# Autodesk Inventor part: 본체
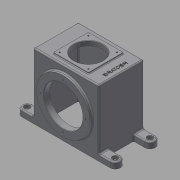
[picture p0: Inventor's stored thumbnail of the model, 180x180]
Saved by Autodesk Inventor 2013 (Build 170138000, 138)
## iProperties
Created: 2016-11
Part Number: 본체
Material: 일반
Document SubType Name: Modeling
Designer: mduedu
Density: 1 g/cm^3
Author: mduedu
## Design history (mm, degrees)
sketch "스케치1"
  geometry: L1 (-80, 0)-(80, 0); L2 (80, 0)-(80, 160); L3 (80, 160)-(-80, 160); L4 (-80, 160)-(-80, 0); 2 further points
  constraints: 8 end point, 2 parallel, 1 coincident, 1 horizontal, 1 midpoint, 1 perpendicular
  dimensions: "d0" = 160 distance of L2.end L3.end; "d2" = 160 distance of L1.end L2.end
extrude "돌출1" new body sketch "스케치1" stored distance "d3" = 110; taper "d4" = 0 deg
sketch "스케치2"
  geometry: L1 (-80, -55)-(-80, 55) reference; L2 (-80, -55)-(-120, -55); L3 (-120, -55)-(-120, 55); L4 (-120, 55)-(-80, 55); L5 (-80, 55)-(-80, -55); 1 further point
  constraints: 8 end point, 2 parallel, 1 horizontal, 1 perpendicular
  dimensions: "d5" = 40 distance of L1.end L3.end
extrude "돌출2" join sketch "스케치2" distance "d6" = 15; taper "d7" = 0 deg
sketch "스케치3"
  geometry: L1 (80, 55)-(80, -55) reference; L2 (120, -55)-(120, 55) reference; L3 (80, 30)-(120, 30); L4 (120, 30)-(120, -30); L5 (120, -30)-(80, -30); L6 (80, -30)-(80, 30); L7 (-80, -55)-(120, -55) reference; L8 (-80, 55)-(120, 55) reference; 1 further point
  constraints: 8 end point, 2 parallel, 2 point on line, 1 horizontal, 1 perpendicular
  dimensions: "d8" = 25 distance between parallel lines of L5 L7; "d9" = 25 distance between parallel lines of L3 L8 (= d8)
extrude "돌출3" cut sketch "스케치3" stored distance "d10" = 15; taper "d11" = 0 deg
fillet "모깎기1"
fillet "모깎기2"
hole "구멍1" diameter "d14" = 9; stored, may be unused: countersink angle "d18" = 90 deg, drill point angle "d20" = 118 deg; dims "d12" = 10, "d13" = 10, "d15" = 6, "d16" = 14, "d17" = 8, "d19" = 8
fillet "모깎기3" dims "d21" = 3
fillet "모깎기4" dims "d22" = 3
sketch "스케치4"
  geometry: L1 (80, 160)-(-80, 160) reference; L2 (-80, 17.196)-(-80, 160) reference; L3 (80, 17.196)-(80, 160) reference; L4 (-72, 0)-(-72, 152); L5 (-72, 152)-(72, 152); L6 (72, 152)-(72, 0); L7 (-72, 0)-(72, 0); 2 further points
  constraints: 8 end point, 1 coincident, 1 midpoint, 1 perpendicular
  dimensions: "d23" = 8 distance between parallel lines of L5 L1; "d24" = 8 distance between parallel lines of L3 L6 (= d23); "d25" = 8 distance between parallel lines of L2 L4 (= d23)
extrude "돌출4" cut sketch "스케치4" stored distance "d26" = 94; taper "d27" = 0 deg
fillet "모깎기5" dims "d28" = 3
fillet "모깎기6" dims "d29" = 3
fillet "모깎기7" dims "d30" = 3
fillet "모깎기8" dims "d31" = 3
sketch "스케치5"
  geometry: C1 r 65 at (0, 80); 1 further point
  constraints: 1 centre point, 1 vertical alignment
  dimensions: "d32" = 130 diameter of C1; "d33" = 80 distance of C1.centre point (0, 0)
extrude "돌출5" join sketch "스케치5" distance "d34" = 7; taper "d35" = 0 deg
sketch "스케치6"
  geometry: C1 r 35 at (77, 51.5); 2 further points
  constraints: 1 centre point, 1 coincident, 1 vertical alignment
  dimensions: "d36" = 70 diameter of C1; "d77" = 0.5 distance of point (77, 52) point (77, 51.5)
extrude "돌출6" cut sketch "스케치6" stored distance "d37" = 7; taper "d38" = 0 deg
sketch "스케치7"
  geometry: L1 (34.5, 9)-(119.5, 9); L2 (119.5, 9)-(119.5, 94); L3 (119.5, 94)-(34.5, 94); L4 (34.5, 94)-(34.5, 9); L5 (34.5, 9)-(119.5, 94); L6 (119.5, 9)-(34.5, 94); C1 r 35 at (77, 51.5) reference; 2 further points
  constraints: 12 end point, 3 midpoint, 2 parallel, 1 coincident, 1 horizontal, 1 perpendicular
  dimensions: "d39" = 85 distance of L3.end L2.end; "d40" = 85 distance of L1.end L2.end (= d39)
extrude "돌출7" join sketch "스케치7" distance "d41" = 3; taper "d42" = 0 deg
fillet "모깎기9" dims "d43" = 3
fillet "모깎기10" dims "d44" = 2
hole "구멍2" diameter "d47" = 95; stored, may be unused: countersink angle "d51" = 90 deg, drill point angle "d53" = 118 deg; dims "d45" = 10, "d46" = 10, "d48" = 6, "d49" = 14, "d50" = 8, "d52" = 8
chamfer "모따기1" distance "d54" = 1; stored, may be unused: second distance "d55" = 2, angle "d56" = 45 deg
sketch "스케치8"
  geometry: C1 r 65 at (0, 80) reference; C2 r 31.5 at (0, 80); 1 further point
  constraints: 1 centre point, 1 coincident
  dimensions: "d57" = 63 diameter of C2
extrude "돌출8" join sketch "스케치8" distance "d58" = 14; taper "d59" = 0 deg
hole "구멍3" diameter "d62" = 30; stored, may be unused: countersink angle "d66" = 90 deg, drill point angle "d68" = 0 deg; dims "d60" = 10, "d61" = 10, "d63" = 6, "d64" = 47, "d65" = 14, "d67" = 17
fillet "모깎기11" dims "d69" = 3
fillet "모깎기12" dims "d70" = 3
fillet "모깎기13" dims "d71" = 0.5
chamfer "모따기2" distance "d72" = 1; stored, may be unused: second distance "d73" = 2, angle "d74" = 45 deg
fillet "모깎기14" dims "d75" = 3
sketch "스케치9"
  geometry: L1 (157, 0)-(157, 104) reference; L2 (77, 52)-(157, 52); 1 further point
  constraints: 2 end point, 1 midpoint, 1 point on line, 1 other
  dimensions: "d78" = 65 distance of point (142, 52) L2.start
feature "엠보싱1" sketch "스케치9" dims "d79" = 0.5, "d80" = 0
sketch "스케치10"
  geometry: 4 further points
  constraints: 4 other
hole "구멍4" sketch "스케치10" at (0, -55), (55, 0), (-55, 0), (0, 55) diameter "d81" = 3.242; stored, may be unused: countersink angle "d85" = 90 deg, drill point angle "d87" = 120 deg; dims "d82" = 6.6, "d83" = 4, "d84" = 2, "d86" = 8.6
sketch "스케치11"
  geometry: 4 further points
  constraints: 4 other
hole "구멍5" sketch "스케치11" at (42, 86.5), (112, 86.5), (112, 16.5), (42, 16.5) diameter "d88" = 3.242; stored, may be unused: countersink angle "d92" = 90 deg, drill point angle "d94" = 120 deg; dims "d89" = 6.6, "d90" = 4, "d91" = 2, "d93" = 8.6
node "솔리드1"
mirror "대칭1"
mirror "대칭2"
mirror "대칭3"
